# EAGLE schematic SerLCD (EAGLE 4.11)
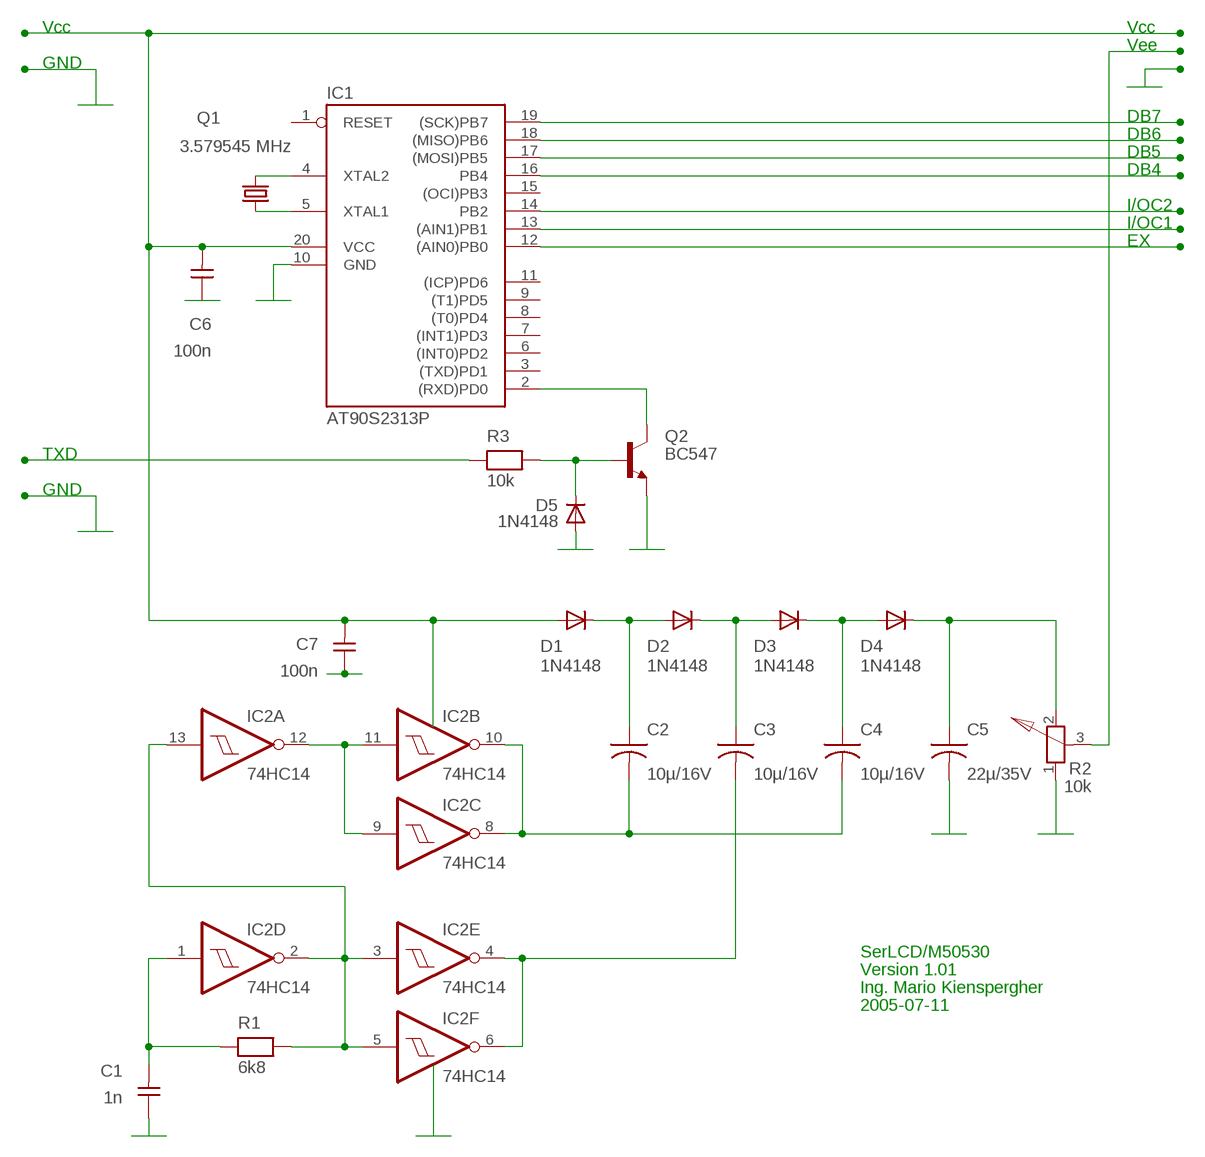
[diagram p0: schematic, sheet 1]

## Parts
C1  1n  CAPNP-5  [C-5]
C2  10µ/16V  CAP-2,5  [C-2,5]
C3  10µ/16V  CAP-2,5  [C-2,5]
C4  10µ/16V  CAP-2,5  [C-2,5]
C5  22µ/35V  CAP-2,5  [C-2,5]
C6  100n  CAPNP-2,5  [C-2,5]
C7  100n  CAPNP-2,5  [C-2,5]
D1  1N4148  [DO35-10]
D2  1N4148  [DO35-10]
D3  1N4148  [DO35-10]
D4  1N4148  [DO35-10]
D5  1N4148  [DO35-10]
IC1  AT90S2313P  [DIL20]
IC2  74HC14  74AC14N  [DIL14]
Q1  3.579545 MHz  CRYTALHC49S  [HC49/S]
Q2  BC547  [TO92]
R1  6k8  RESEU-10  [R-10]
R2  10k  POT-S  [PT-10S]
R3  10k  RESEU-10  [R-10]

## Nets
N$1: IC2.2(D:O) IC2.3(E:I) IC2.5(F:I) IC2.13(A:I) R1.2
N$2: IC2.9(C:I) IC2.11(B:I) IC2.12(A:O)
N$3: C2.2 C4.2 IC2.8(C:O) IC2.10(B:O)
N$4: C3.2 IC2.4(E:O) IC2.6(F:O)
N$5: C1.2 IC2.1(D:I) R1.1
N$6: IC1.5(XTAL1) Q1.1
N$7: IC1.4(XTAL2) Q1.2
N$8: C1.1
N$9: C2.1 D1.C D2.A
N$10: C3.1 D2.C D3.A
N$11: C4.1 D3.C D4.A
N$12: C5.1 D4.C R2.2
N$14: C5.2
N$16: IC1.10(GND)
N$18: C6.2 C7.2 D1.A IC1.20(VCC)
N$19: R2.1
N$23: C7.1
N$24: C6.1
N$25: IC1.19((SCK)PB7)
N$26: IC1.18((MISO)PB6)
N$27: IC1.17((MOSI)PB5)
N$28: IC1.16(PB4)
N$29: IC1.14(PB2)
N$30: IC1.13((AIN1)PB1)
N$31: IC1.12((AIN0)PB0)
N$32: R2.3
N$33: Q2.1(E)
N$35: R3.1
N$36: D5.C R3.2
N$37: IC1.2((RXD)PD0) Q2.3(C)
N$38: D5.A
Unconnected: IC1.1(RESET) IC1.3((TXD)PD1) IC1.6((INT0)PD2) IC1.7((INT1)PD3) IC1.8((T0)PD4) IC1.9((T1)PD5) IC1.11((ICP)PD6) IC1.15((OCI)PB3) Q2.2(B)

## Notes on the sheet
- Vcc | Vcc
- Vee
- GND
- DB7
- DB6
- DB5
- DB4
- I/OC2
- I/OC1
- EX
- TXD
- GND
- SerLCD/M50530
- Version 1.01
- Ing. Mario Kienspergher
- 2005-07-11

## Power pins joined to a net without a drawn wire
GND: IC2.7(P:GND)
VCC: IC2.14(P:VCC)

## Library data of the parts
C1 = discrete:CAPNP-5
C2-C5 = discrete:CAP-2,5
C6 C7 = discrete:CAPNP-2,5
D1-D5 = diode:1N4148: DIODE
IC1 = atmel:AT90S2313: MICROCONTROLLER 2 Kbytes FLASH 128 bytes SRAM 128 bytes EEPROM UART
IC2 = 74xx-eu:74*14: Hex schmitt trigger INVERTER
Q1 = crystal:CRYTAL: CRYSTAL
Q2 = transistor-npn:BC547*: NPN Transistor
R1 R3 = discrete:RESEU-10
R2 = discrete:POT-S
